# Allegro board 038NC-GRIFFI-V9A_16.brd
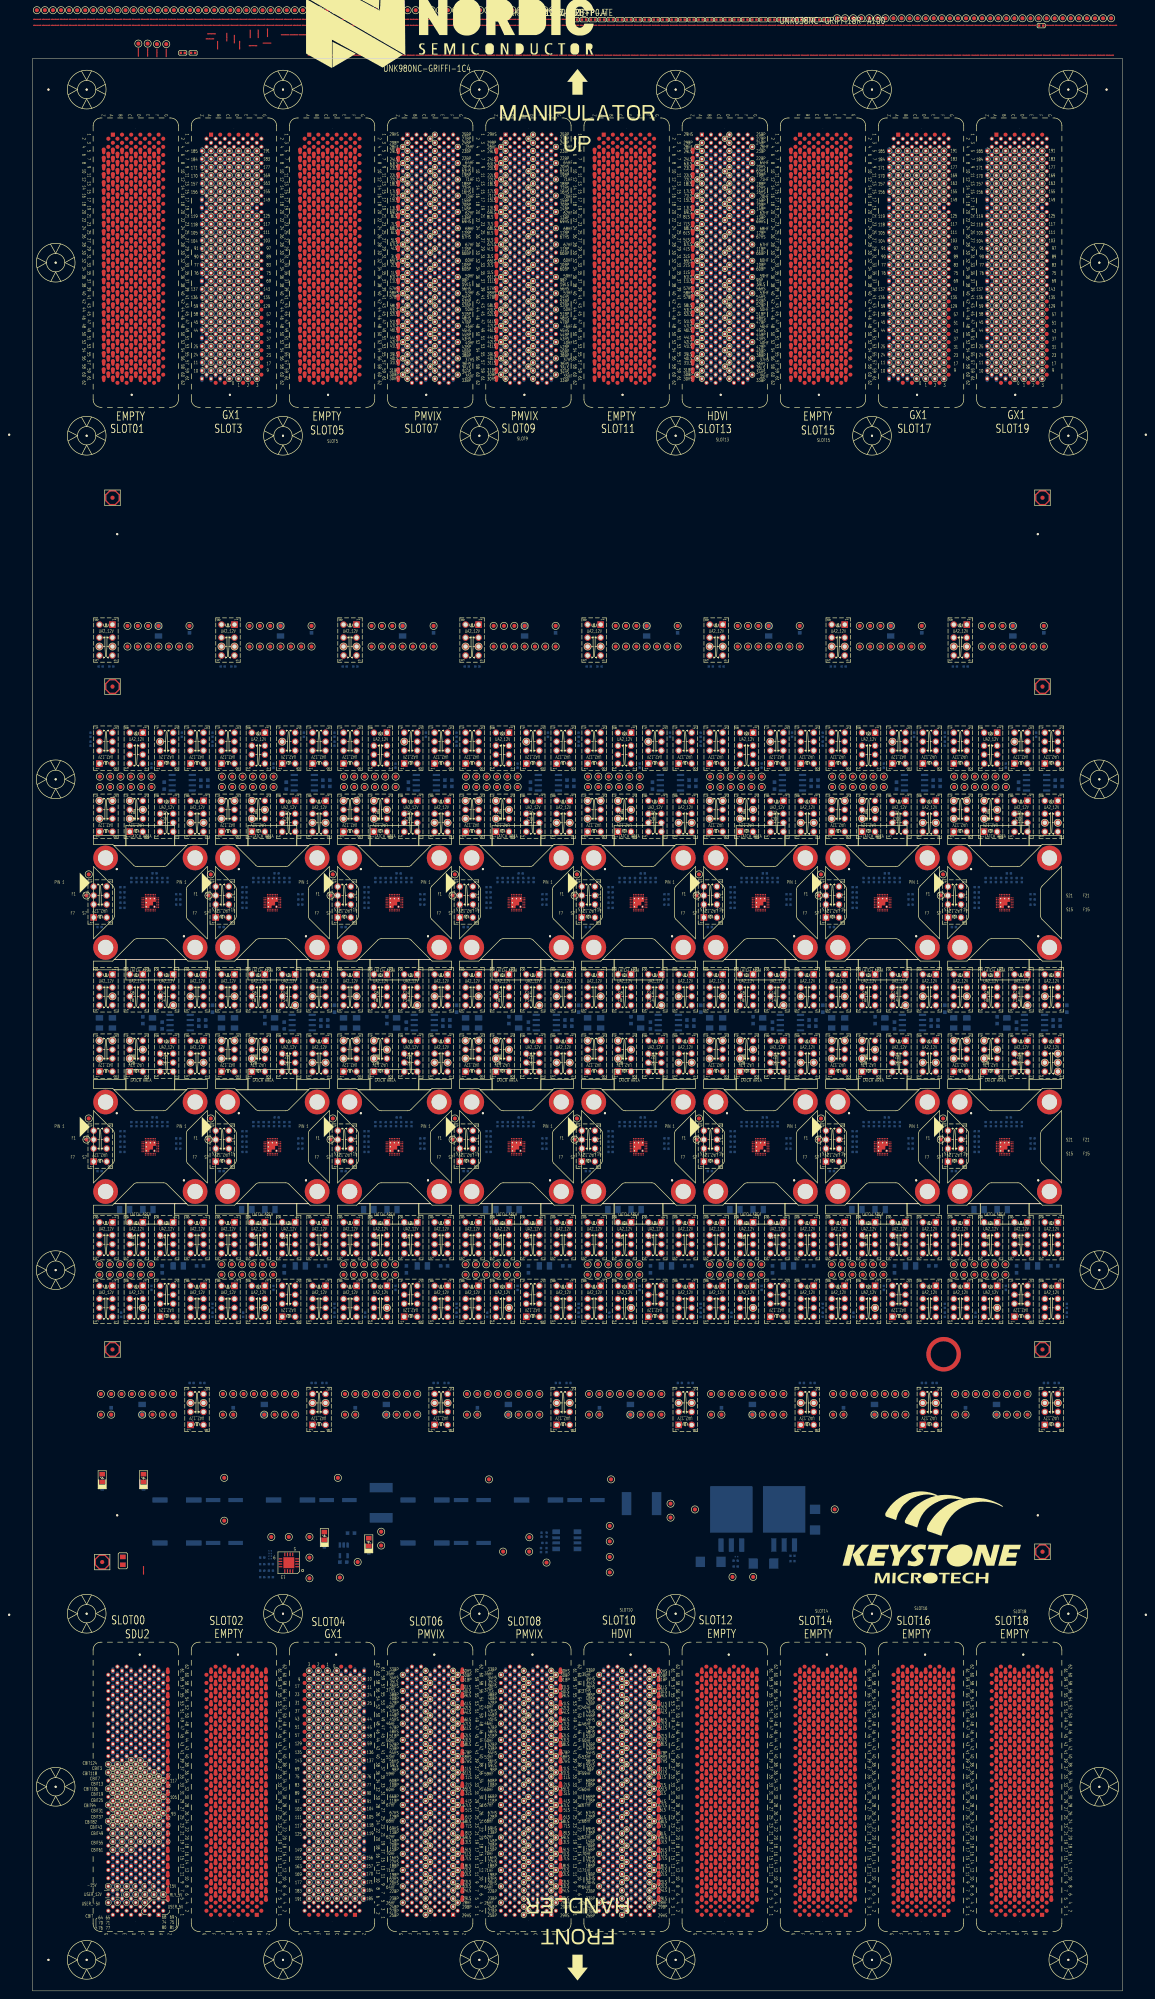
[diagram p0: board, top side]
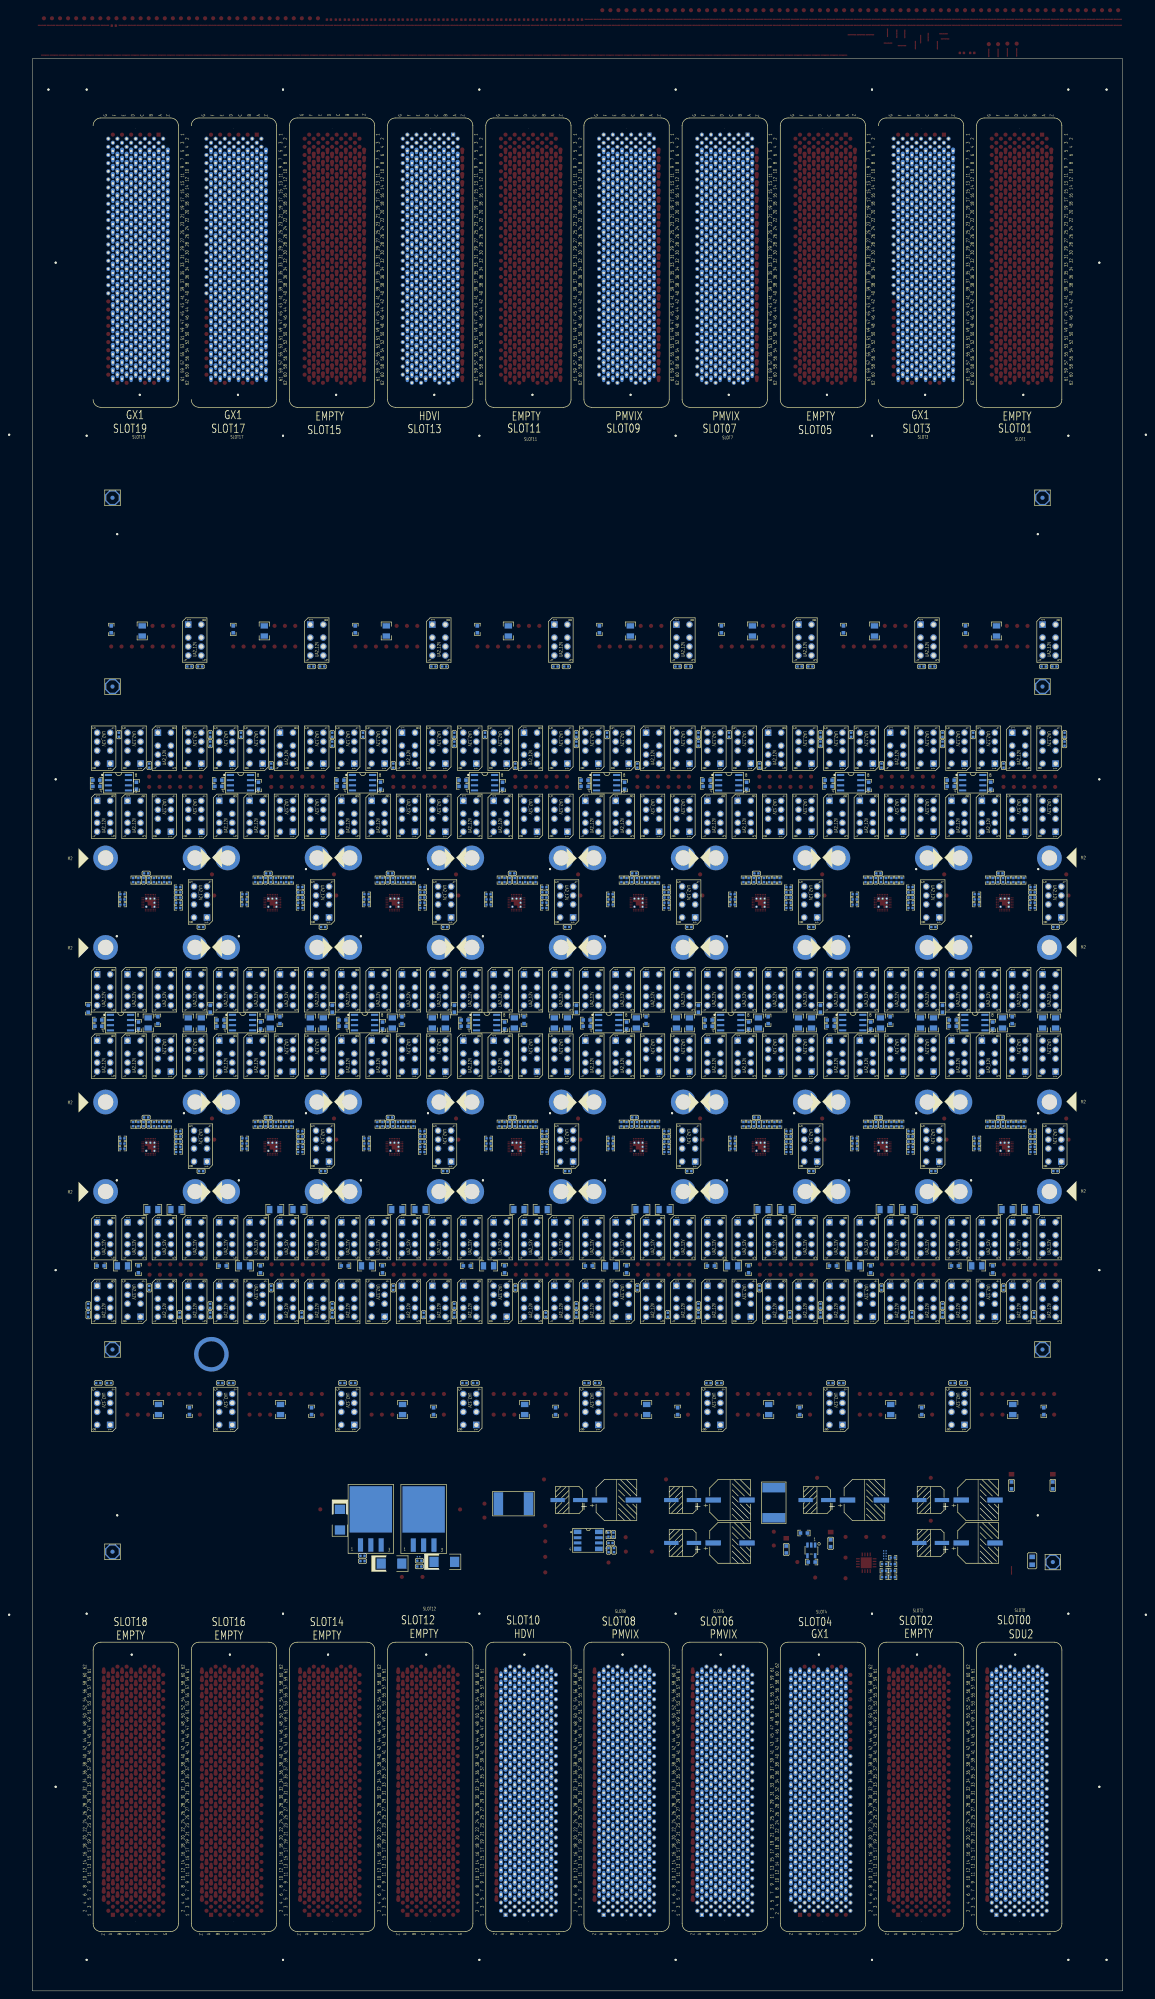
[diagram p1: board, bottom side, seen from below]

Outline 267.97 x 474.98 mm; copper layers: TOP, L02_GND, L03_SIGNAL, L04_GND, L05_SIGNAL, L06_GND, L07_SIGNAL, L08_GND, L09_PWR, L10_PWR, L11_GND, L12_PWR, L13_PWR, L14_GND, L15_USER, L16_CBIT, L17_GND, L18_PWR, L19_PWR, L20_GND, L21_PWR, L22_PWR, L23_GND, L24_SIGNAL, L25_GND, L26_SIGNAL, L27_GND, L28_SIGNAL, L29_GND, L30_SIGNAL, L31_GND, BOTTOM. Coordinates in mm from the lower left corner of the outline.

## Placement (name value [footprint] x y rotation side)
BC1  100U-50-E-S-6.6X6.6  [EC_6P3X7P7MM_S]  75.12 120.65 270 bottom
BC2  47U-100-E-S10X10-NI  [ECS_10X10MM_H10P5]  63.45 120.65 90 bottom
BC3  100U-50-E-S-6.6X6.6  [EC_6P3X7P7MM_S]  108.14 110.11 270 bottom
BC4  47U-100-E-S10X10-NI  [ECS_10X10MM_H10P5]  96.47 110.11 90 bottom
BC5  100U-50-E-S-6.6X6.6  [EC_6P3X7P7MM_S]  47.18 120.65 270 bottom
BC6  47U-100-E-S10X10-NI  [ECS_10X10MM_H10P5]  35.51 120.65 90 bottom
BC7  100U-50-E-S-6.6X6.6  [EC_6P3X7P7MM_S]  108.14 120.65 270 bottom
BC8  47U-100-E-S10X10-NI  [ECS_10X10MM_H10P5]  96.47 120.65 90 bottom
BC10  47U-100-E-S10X10-NI  [ECS_10X10MM_H10P5]  124.41 120.65 90 bottom
BC11  100U-50-E-S-6.6X6.6  [EC_6P3X7P7MM_S]  136.08 120.65 270 bottom
BC12  47U-100-E-S10X10-NI  [ECS_10X10MM_H10P5]  35.51 110.11 90 bottom
BC13  100U-50-E-S-6.6X6.6  [EC_6P3X7P7MM_S]  47.18 110.11 270 bottom
BD1  BD120-3.5A-S8-LA  [FB0805]  22.23 105.71 90 top
BD2  BD120-3.5A-S8-LA  [FB0805]  22.23 105.71 90 bottom
BR1  560-1-S6  [R0603]  71.76 110.03 270 bottom
BR2  560-1-S6  [R0603]  82.68 108.5 270 bottom
BR3  560-1-S6  [R0603]  27.31 124.25 270 bottom
BR4  1K-1-S6  [R0603]  17.15 124.25 270 bottom
C14  1U-16-X5R-S4-YA  [C0402]  126.4 112.15 90 bottom
C84  1U-16-X6S-S4-TY  [C0402]  56.49 106.51 180 bottom
C85  1U-16-X6S-S4-TY  [C0402]  56.49 103.28 180 bottom
C86  1U-16-X6S-S4-TY  [C0402]  56.49 104.88 180 bottom
C87  0.1U-10-X7R-S4-MU-1  [C0402]  58.62 104.91 0 bottom
C88  0.1U-10-X7R-S4-MU-1  [C0402]  58.62 103.28 0 bottom
C89  0.1U-10-X7R-S4-MU-1  [C0402]  56.49 101.68 180 bottom
C90  100P-50-X8R-S4-KEMET  [C0402]  58.62 101.68 0 bottom
C99  10U-35-T-SC  [CODE_C]  166.73 105.45 180 bottom
C100  10U-35-T-SC  [CODE_C]  179.71 105.04 180 bottom
C101  10U-35-T-SC  [CODE_C]  192.38 115.82 270 bottom
C102  1U-25-X7R-S6-WA  [C0603]  78.31 112.54 0 bottom
C103  1U-25-X7R-S6-WA  [C0603]  76.41 105.41 0 bottom
FD1  FD_040  [FD_040_V2]  17.15 105.41 0 top
FD2  FD_040  [FD_040_V2]  19.69 157.66 0 top
FD3  FD_040  [FD_040_V2]  19.69 320.62 0 top
FD4  FD_040  [FD_040_V2]  19.69 367.03 0 top
FD5  FD_040  [FD_040_V2]  248.29 367.03 0 top
FD6  FD_040  [FD_040_V2]  248.29 320.62 0 top
FD7  FD_040  [FD_040_V2]  248.29 157.66 0 top
FD8  FD_040  [FD_040_V2]  248.29 107.95 0 top
FD9  FD_040  [FD_040_V2]  17.15 105.41 180 bottom
FD10  FD_040  [FD_040_V2]  19.69 157.66 180 bottom
FD11  FD_040  [FD_040_V2]  19.69 320.62 180 bottom
FD12  FD_040  [FD_040_V2]  19.69 367.03 180 bottom
FD13  FD_040  [FD_040_V2]  248.29 367.03 180 bottom
FD14  FD_040  [FD_040_V2]  248.29 320.62 180 bottom
FD15  FD_040  [FD_040_V2]  248.29 157.66 180 bottom
FD16  FD_040  [FD_040_V2]  248.29 107.95 180 bottom
FUSE1  2920L200-2A-S7.98X5.44  [FUSE_2920_H45]  149.73 119.76 0 bottom
FUSE2  2920L200-2A-S7.98X5.44  [FUSE_2920_H45]  85.73 119.99 270 bottom
H1  M3-HOLE  [M3_NPTH169]  20.84 116.9 0 top
H2  M3-HOLE  [M3_NPTH169]  20.84 358.08 0 top
H3  M3-HOLE  [M3_NPTH169]  247.13 358.08 0 top
H4  M3-HOLE  [M3_NPTH169]  247.13 116.9 0 top
LOGO1  -  [LOGO_NC_NORDIC]  98.78 473.44 0 top
LOGO2  -  [LOGO_KT_KSMT]  217.98 104.48 0 top
M1  -  [PG_LTXDX_F_X1_OUTLINE_FULL_V2]  133.99 237.49 0 top
NOREF  -  []  83.93 229.18 90 top
NOREF#2  -  []  87.13 244.47 90 top
NOREF#3  -  []  75.06 203.86 0 top
NOREF#4  -  []  237.13 165.7 90 top
NOREF#5  -  []  92.17 456.29 0 top
NOREF#6  -  []  196.47 304.88 90 top
NOREF#7  -  []  164.98 283.99 0 top
NOREF#8  -  []  64.59 289.34 90 top
NOREF#9  -  []  121.39 301.68 0 top
NOREF#10  -  []  87.13 303.88 90 top
NOREF#11  -  []  124.59 244.47 90 top
NOREF#12  -  []  134.98 223.99 0 top
NOREF#13  -  []  250.89 283.29 90 top
NOREF#14  -  []  158.86 292.54 0 top
NOREF#15  -  []  213.61 203.06 0 top
NOREF#16  -  []  150.18 205.47 90 top
NOREF#17  -  []  106.47 288.14 90 top
NOREF#18  -  []  29.32 208.11 315 top
NOREF#19  -  []  57.13 246.67 90 top
NOREF#20  -  []  210.18 265.47 90 top
NOREF#21  -  []  128.86 307.08 90 top
NOREF#22  -  []  27.13 242.27 90 top
NOREF#23  -  []  117.13 170.1 90 top
NOREF#24  -  []  195.06 269.26 90 top
NOREF#25  -  []  71.4 298.06 90 top
NOREF#26  -  []  94.59 242.27 90 top
NOREF#27  -  []  162.06 167.9 90 top
NOREF#28  -  []  212.82 456.29 0 top
NOREF#29  -  []  218.86 292.54 0 top
NOREF#30  -  []  117.13 301.68 90 top
NOREF#31  -  []  232.1 458.49 0 top
NOREF#32  -  []  87.13 185.73 90 top
NOREF#33  -  []  116.3 396.29 0 top
NOREF#34  -  []  115.97 179.68 90 top
NOREF#35  -  []  139.67 242.27 90 top
NOREF#36  -  []  132.78 117.35 0 top
NOREF#37  -  []  232.08 83.81 0 top
NOREF#38  -  []  45.92 284.14 90 top
NOREF#39  -  []  70.9 237.58 90 top
NOREF#40  -  []  83.93 249.87 0 top
NOREF#41  -  []  38.39 193.49 45 top
NOREF#42  -  []  119.39 209.51 0 top
NOREF#43  -  []  184.59 181.33 90 top
NOREF#44  -  []  229.67 183.53 90 top
NOREF#45  -  []  38.86 173.3 0 top
NOREF#46  -  []  131.4 296.54 90 top
NOREF#47  -  []  232.98 286.49 0 top
NOREF#48  -  []  151.39 171.1 90 top
NOREF#49  -  []  128.31 138.32 90 top
NOREF#50  -  []  16.47 231.38 90 top
NOREF#51  -  []  185.02 225.18 0 top
NOREF#52  -  []  72.67 392.33 90 top
NOREF#53  -  []  136.47 225.98 0 top
NOREF#54  -  []  149.42 18.69 0 top
NOREF#55  -  []  121.39 188.93 0 top
NOREF#56  -  []  93.43 164.05 90 top
NOREF#57  -  []  121.39 168.9 90 top
NOREF#58  -  []  19.67 328.26 90 top
NOREF#59  -  []  57.13 185.73 90 top
NOREF#60  -  []  45.06 267.06 90 top
NOREF#61  -  []  196.47 225.98 0 top
NOREF#62  -  []  87.13 301.68 90 top
NOREF#63  -  []  207.36 208.69 0 top
NOREF#64  -  []  252.06 289.34 90 top
NOREF#65  -  []  200.48 270.77 0 top
NOREF#66  -  []  87.13 165.7 90 top
NOREF#67  -  []  151.67 18.69 90 top
NOREF#68  -  []  72.06 242.27 90 top
NOREF#69  -  []  147.13 181.33 90 top
NOREF#70  -  []  45.92 225.18 90 top
NOREF#71  -  []  44.99 281.49 90 top
NOREF#72  -  []  20.22 174.1 0 top
NOREF#73  -  []  135.06 203.86 90 top
NOREF#74  -  []  188.66 177.76 90 top
NOREF#75  -  []  79.67 170.1 90 top
NOREF#76  -  []  42.06 170.1 90 top
NOREF#77  -  []  130.89 179.68 90 top
NOREF#78  -  []  147.36 208.69 0 top
NOREF#79  -  []  127.36 333.84 90 top
NOREF#80  -  []  180.84 300.88 90 top
NOREF#81  -  []  244.59 287.14 90 top
NOREF#82  -  []  140.74 275.74 0 top
NOREF#83  -  []  68.86 304.88 90 top
NOREF#84  -  []  158.66 177.76 90 top
NOREF#85  -  []  61.4 188.93 0 top
NOREF#86  -  []  188.86 304.88 90 top
NOREF#87  -  []  164.55 18.69 0 top
NOREF#88  -  []  184.59 185.73 90 top
NOREF#89  -  []  61.4 249.87 0 top
NOREF#90  -  []  181.39 307.08 90 top
NOREF#91  -  []  229.67 167.9 90 top
NOREF#92  -  []  169.67 328.26 90 top
NOREF#93  -  []  83.93 284.94 0 top
NOREF#94  -  []  248.86 307.08 90 top
NOREF#95  -  []  58.35 207.84 315 top
NOREF#96  -  []  147.13 301.68 90 top
NOREF#97  -  []  131.02 336.66 0 top
NOREF#98  -  []  27.64 268.84 0 top
NOREF#99  -  []  237.13 301.68 90 top
NOREF#100  -  []  19.67 332.66 90 top
NOREF#101  -  []  208.35 267.84 315 top
NOREF#102  -  []  173.93 309.28 0 top
NOREF#103  -  []  211.01 266.29 90 top
NOREF#104  -  []  205.94 234.38 0 top
NOREF#105  -  []  57.82 106.54 0 top
NOREF#106  -  []  192.06 289.34 90 top
NOREF#107  -  []  248.86 301.68 0 top
NOREF#108  -  []  48.48 310.08 0 top
NOREF#109  -  []  205.97 240.62 90 top
NOREF#110  -  []  19.67 185.73 90 top
NOREF#111  -  []  162.66 103.55 90 top
NOREF#112  -  []  43.91 396.29 0 top
NOREF#113  -  []  119.29 267.51 45 top
NOREF#114  -  []  102.06 185.73 90 top
NOREF#115  -  []  241.39 301.68 90 top
NOREF#116  -  []  98.31 138.32 90 top
NOREF#117  -  []  136.47 288.14 90 top
NOREF#118  -  []  123.43 164.05 90 top
NOREF#119  -  []  192.06 242.27 90 top
NOREF#120  -  []  15.06 263.86 90 top
NOREF#121  -  []  22.99 188.49 90 top
NOREF#122  -  []  225.06 263.86 0 top
NOREF#123  -  []  101.02 174.1 0 top
NOREF#124  -  []  40.9 237.58 90 top
NOREF#125  -  []  117.79 209.51 0 top
NOREF#126  -  []  151.39 165.7 90 top
NOREF#127  -  []  210.84 164.9 90 top
NOREF#128  -  []  192.06 165.7 90 top
NOREF#129  -  []  72.06 244.47 90 top
NOREF#130  -  []  210.65 236.45 90 top
NOREF#131  -  []  16.47 229.18 90 top
NOREF#132  -  []  208.37 267.15 315 top
NOREF#133  -  []  91.4 171.1 90 top
NOREF#134  -  []  248.86 139.12 90 top
NOREF#135  -  []  240.18 205.47 90 top
NOREF#136  -  []  181.39 301.68 0 top
NOREF#137  -  []  95.02 225.18 0 top
NOREF#138  -  []  194.51 203.06 90 top
NOREF#139  -  []  15.07 283.29 90 top
NOREF#140  -  []  153.43 179.68 90 top
NOREF#141  -  []  90.84 164.9 90 top
NOREF#142  -  []  120.26 120.65 0 top
NOREF#143  -  []  108.48 250.67 0 top
NOREF#144  -  []  14.99 283.99 0 top
NOREF#145  -  []  228.36 240.62 90 top
NOREF#146  -  []  17.99 196.49 90 top
NOREF#147  -  []  232.98 188.49 90 top
NOREF#148  -  []  172.98 248.49 90 top
NOREF#149  -  []  42.48 284.14 0 top
NOREF#150  -  []  113.93 309.28 0 top
NOREF#151  -  []  90.84 300.88 90 top
NOREF#152  -  []  123.41 234.38 0 top
NOREF#153  -  []  117.13 165.7 90 top
NOREF#154  -  []  71.4 296.54 90 top
NOREF#155  -  []  120.67 176.51 90 top
NOREF#156  -  []  244.59 181.33 90 top
NOREF#157  -  []  27.13 185.73 90 top
NOREF#158  -  []  61.2 115.65 0 top
NOREF#159  -  []  57.64 268.84 0 top
NOREF#160  -  []  110.74 275.74 0 top
NOREF#161  -  []  211.39 188.93 0 top
NOREF#162  -  []  225.06 209.26 90 top
NOREF#163  -  []  109.94 300.88 0 top
NOREF#164  -  []  61.4 292.54 0 top
NOREF#165  -  []  210.18 265.86 90 top
NOREF#166  -  []  151.01 206.29 90 top
NOREF#167  -  []  207.13 185.73 90 top
NOREF#168  -  []  191.4 298.06 90 top
NOREF#169  -  []  93.41 189.73 0 top
NOREF#170  -  []  76.47 284.94 90 top
NOREF#171  -  []  252.06 284.94 90 top
NOREF#172  -  []  241.39 165.7 0 top
NOREF#173  -  []  83.93 225.98 90 top
NOREF#174  -  []  203.93 231.38 90 top
NOREF#175  -  []  233.93 188.93 0 top
NOREF#176  -  []  143.93 225.98 90 top
NOREF#177  -  []  153.43 240.62 90 top
NOREF#178  -  []  78.48 250.67 0 top
NOREF#179  -  []  25.97 179.68 90 top
NOREF#180  -  []  217.23 199.24 90 top
NOREF#181  -  []  113.38 225.18 90 top
NOREF#182  -  []  89.29 267.51 45 top
NOREF#183  -  []  188.39 193.49 45 top
NOREF#184  -  []  132.06 246.67 90 top
NOREF#185  -  []  149.29 267.51 45 top
NOREF#186  -  []  139.67 181.33 90 top
NOREF#187  -  []  27.13 306.08 90 top
NOREF#188  -  []  144.63 116.76 0 top
NOREF#189  -  []  250.89 237.58 90 top
NOREF#190  -  []  70.89 224.33 90 top
NOREF#191  -  []  196.47 188.93 0 top
NOREF#192  -  []  150.84 300.88 90 top
NOREF#193  -  []  135.58 458.49 0 top
NOREF#194  -  []  76.47 335.86 0 top
NOREF#195  -  []  177.13 170.1 90 top
NOREF#196  -  []  79.94 300.88 0 top
NOREF#197  -  []  136.47 173.3 0 top
NOREF#198  -  []  235.88 237.76 90 top
NOREF#199  -  []  134.51 203.06 90 top
NOREF#200  -  []  59.32 208.11 315 top
NOREF#201  -  []  59.29 267.51 45 top
NOREF#202  -  []  192.38 113.28 90 top
NOREF#203  -  []  57.82 107.84 0 top
NOREF#204  -  []  225.06 203.86 90 top
NOREF#205  -  []  22.53 251.52 0 top
NOREF#206  -  []  109.94 164.9 0 top
NOREF#207  -  []  168.48 250.67 0 top
NOREF#208  -  []  33.97 14.59 90 top
NOREF#209  -  []  78.36 164.05 90 top
NOREF#210  -  []  233.93 284.94 0 top
NOREF#211  -  []  184.59 242.27 90 top
NOREF#212  -  []  169.67 167.9 90 top
NOREF#213  -  []  76.47 231.38 90 top
NOREF#214  -  []  38.86 188.93 0 top
NOREF#215  -  []  23.93 249.87 0 top
NOREF#216  -  []  88.65 266.87 45 top
NOREF#217  -  []  160.89 224.33 90 top
NOREF#218  -  []  104.99 221.49 90 top
NOREF#219  -  []  85.94 234.38 0 top
NOREF#220  -  []  77.99 256.49 90 top
NOREF#221  -  []  222.06 185.73 90 top
NOREF#222  -  []  147.13 244.47 90 top
NOREF#223  -  []  42.06 181.33 90 top
NOREF#224  -  []  195.06 263.86 90 top
NOREF#225  -  []  120.18 265.86 90 top
NOREF#226  -  []  28.35 207.84 45 top
NOREF#227  -  []  94.59 185.73 90 top
NOREF#228  -  []  203.93 290.34 90 top
NOREF#229  -  []  240.33 266.14 90 top
NOREF#230  -  []  31.4 171.1 90 top
NOREF#231  -  []  105.06 267.06 90 top
NOREF#232  -  []  20.61 142.44 90 top
NOREF#233  -  []  235.94 189.73 0 top
NOREF#234  -  []  159.71 458.49 0 top
NOREF#235  -  []  16.47 288.14 90 top
NOREF#236  -  []  139.67 185.73 90 top
NOREF#237  -  []  81.95 111.4 0 top
NOREF#238  -  []  4.17 164.05 90 top
NOREF#239  -  []  244.59 185.73 90 top
NOREF#240  -  []  175.97 179.68 90 top
NOREF#241  -  []  237.13 167.9 90 top
NOREF#242  -  []  200.73 215.74 0 top
NOREF#243  -  []  41.4 295.64 90 top
NOREF#244  -  []  34.6 230.38 90 top
NOREF#245  -  []  158.86 144.52 90 top
NOREF#246  -  []  252.06 183.53 90 top
NOREF#247  -  []  118.37 207.15 315 top
NOREF#248  -  []  106.38 389.27 90 top
NOREF#249  -  []  158.39 193.49 45 top
NOREF#250  -  []  116.29 20.69 90 top
NOREF#251  -  []  26.58 127.15 0 top
NOREF#252  -  []  45.06 207.06 90 top
NOREF#253  -  []  208.35 267.84 45 top
NOREF#254  -  []  102.06 228.18 90 top
NOREF#255  -  []  23.93 188.93 0 top
NOREF#256  -  []  227.98 256.49 90 top
NOREF#257  -  []  140.48 210.77 0 top
NOREF#258  -  []  35.02 284.14 0 top
NOREF#259  -  []  38.86 292.54 0 top
NOREF#260  -  []  154.59 228.18 90 top
NOREF#261  -  []  181.39 165.7 0 top
NOREF#262  -  []  222.06 230.38 90 top
NOREF#263  -  []  57.13 165.7 90 top
NOREF#264  -  []  209.38 209.51 0 top
NOREF#265  -  []  71.03 110.73 90 top
NOREF#266  -  []  17.99 278.49 0 top
NOREF#267  -  []  49.95 300.88 0 top
NOREF#268  -  []  158.86 301.68 0 top
NOREF#269  -  []  178.35 267.84 45 top
NOREF#270  -  []  228.36 224.33 90 top
NOREF#271  -  []  196.47 284.94 0 top
NOREF#272  -  []  140.43 456.29 90 top
NOREF#273  -  []  248.66 177.76 90 top
NOREF#274  -  []  98.86 188.93 0 top
NOREF#275  -  []  16.42 124.95 90 top
NOREF#276  -  []  165.92 300.88 90 top
NOREF#277  -  []  239.32 268.11 315 top
NOREF#278  -  []  188.86 292.54 0 top
NOREF#279  -  []  113.93 225.98 90 top
NOREF#280  -  []  31.01 266.29 90 top
NOREF#281  -  []  13.66 262.21 90 top
NOREF#282  -  []  240.18 265.86 90 top
NOREF#283  -  []  21.07 240.62 90 top
NOREF#284  -  []  66.45 115.65 0 top
NOREF#285  -  []  125.02 225.18 0 top
NOREF#286  -  []  148.37 267.15 315 top
NOREF#287  -  []  25.7 258.99 90 top
NOREF#288  -  []  235.97 179.68 90 top
NOREF#289  -  []  155.02 300.88 0 top
NOREF#290  -  []  49.67 185.73 90 top
NOREF#291  -  []  59.29 207.51 45 top
NOREF#292  -  []  138.48 250.67 0 top
NOREF#293  -  []  188.31 300.88 90 top
NOREF#294  -  []  110.48 270.77 0 top
NOREF#295  -  []  128.31 300.88 90 top
NOREF#296  -  []  120.34 206.14 90 top
NOREF#297  -  []  109.67 181.33 90 top
NOREF#298  -  []  194.98 190.99 90 top
NOREF#299  -  []  76.47 229.18 90 top
NOREF#300  -  []  135.15 107.82 90 top
NOREF#301  -  []  42.61 189.73 0 top
NOREF#302  -  []  147.13 246.67 90 top
NOREF#303  -  []  151.39 301.68 0 top
NOREF#304  -  []  85.94 293.34 0 top
NOREF#305  -  []  195.06 267.06 90 top
NOREF#306  -  []  83.38 284.14 90 top
NOREF#307  -  []  87.79 209.51 0 top
NOREF#308  -  []  207.78 209.51 0 top
NOREF#309  -  []  136.47 290.34 90 top
NOREF#310  -  []  28.65 266.87 45 top
NOREF#311  -  []  85.73 116.29 90 top
NOREF#312  -  []  229.67 328.26 90 top
NOREF#313  -  []  101.02 250.67 0 top
NOREF#314  -  []  247.36 333.84 90 top
NOREF#315  -  []  147.63 268.84 0 top
NOREF#316  -  []  252.06 225.98 90 top
NOREF#317  -  []  215.02 300.88 0 top
NOREF#318  -  []  44.4 110.11 0 top
NOREF#319  -  []  113.93 284.94 0 top
NOREF#320  -  []  90.18 265.86 90 top
NOREF#321  -  []  190.89 283.29 90 top
NOREF#322  -  []  143.93 231.38 90 top
NOREF#323  -  []  118.65 266.87 45 top
NOREF#324  -  []  121.39 307.08 90 top
NOREF#325  -  []  154.59 183.53 90 top
NOREF#326  -  []  38.86 301.68 90 top
NOREF#327  -  []  153.41 174.1 0 top
NOREF#328  -  []  15.07 251.52 0 top
NOREF#329  -  []  16.15 123.41 90 top
NOREF#330  -  []  241.39 168.9 90 top
NOREF#331  -  []  165.06 263.86 90 top
NOREF#332  -  []  143.38 225.18 90 top
NOREF#333  -  []  53.93 225.98 0 top
NOREF#334  -  []  218.86 249.87 0 top
NOREF#335  -  []  23.93 288.14 90 top
NOREF#336  -  []  17.99 256.49 90 top
NOREF#337  -  []  97.55 263.78 0 top
NOREF#338  -  []  72.48 284.14 0 top
NOREF#339  -  []  118.37 267.15 315 top
NOREF#340  -  []  72.06 165.7 90 top
NOREF#341  -  []  164.56 396.29 0 top
NOREF#342  -  []  120.93 392.33 90 top
NOREF#343  -  []  175.94 189.73 0 top
NOREF#344  -  []  210.18 205.86 90 top
NOREF#345  -  []  0 474.98 0 top
NOREF#346  -  []  58.12 107.52 0 top
NOREF#347  -  []  169.67 165.7 90 top
NOREF#348  -  []  181.39 168.9 90 top
NOREF#349  -  []  169.67 170.1 90 top
NOREF#350  -  []  108.36 283.29 90 top
NOREF#351  -  []  190.89 239.1 90 top
NOREF#352  -  []  63.19 457.2 0 top
NOREF#353  -  []  178.65 206.87 45 top
NOREF#354  -  []  248.86 233.58 0 top
NOREF#355  -  []  128.86 292.54 0 top
NOREF#356  -  []  58.12 108.17 0 top
NOREF#357  -  []  195.06 203.86 0 top
NOREF#358  -  []  46.47 335.86 0 top
NOREF#359  -  []  79.28 18.69 0 top
NOREF#360  -  []  177.13 167.9 90 top
NOREF#361  -  []  192.06 183.53 90 top
NOREF#362  -  []  233.93 225.98 0 top
NOREF#363  -  []  82.99 248.49 90 top
NOREF#364  -  []  75.56 104.96 90 top
NOREF#365  -  []  162.06 170.1 90 top
NOREF#366  -  []  207.13 303.88 90 top
NOREF#367  -  []  25.39 17.15 0 top
NOREF#368  -  []  61.4 301.68 90 top
NOREF#369  -  []  63.41 250.67 0 top
NOREF#370  -  []  252.06 170.1 90 top
NOREF#371  -  []  139.67 330.46 90 top
NOREF#372  -  []  237.13 246.67 90 top
NOREF#373  -  []  181.39 171.1 90 top
NOREF#374  -  []  58.35 267.84 45 top
NOREF#375  -  []  27.13 303.88 90 top
NOREF#376  -  []  19.67 244.47 90 top
NOREF#377  -  []  177.13 165.7 90 top
NOREF#378  -  []  60.34 206.14 90 top
NOREF#379  -  []  143.93 284.94 90 top
NOREF#380  -  []  220.89 240.62 90 top
NOREF#381  -  []  197.69 456.29 0 top
NOREF#382  -  []  225.06 267.06 90 top
NOREF#383  -  []  16.47 284.94 90 top
NOREF#384  -  []  64.59 246.67 90 top
NOREF#385  -  []  31.36 120.65 0 top
NOREF#386  -  []  27.13 246.67 90 top
NOREF#387  -  []  241.39 301.68 0 top
NOREF#388  -  []  206.96 208.69 0 top
NOREF#389  -  []  22.53 283.29 90 top
NOREF#390  -  []  25.95 189.73 0 top
NOREF#391  -  []  218.86 173.3 0 top
NOREF#392  -  []  139.67 167.9 90 top
NOREF#393  -  []  128.86 144.52 90 top
NOREF#394  -  []  214.59 244.47 90 top
NOREF#395  -  []  138.36 283.29 90 top
NOREF#396  -  []  175.7 258.99 90 top
NOREF#397  -  []  123.43 300.03 90 top
NOREF#398  -  []  247.55 263.78 0 top
NOREF#399  -  []  46.47 301.68 90 top
NOREF#400  -  []  108.36 164.05 90 top
NOREF#401  -  []  195.06 263.86 0 top
NOREF#402  -  []  199.67 185.73 90 top
NOREF#403  -  []  199.67 330.46 90 top
NOREF#404  -  []  172.46 106.41 0 top
NOREF#405  -  []  183.41 293.34 0 top
NOREF#406  -  []  88.35 267.84 315 top
NOREF#407  -  []  183.84 458.49 0 top
NOREF#408  -  []  14.91 16.49 0 top
NOREF#409  -  []  229.94 300.88 0 top
NOREF#410  -  []  107.99 278.49 0 top
NOREF#411  -  []  175.94 293.34 0 top
NOREF#412  -  []  52.99 286.49 0 top
NOREF#413  -  []  101.17 456.29 0 top
NOREF#414  -  []  224.98 281.49 90 top
NOREF#415  -  []  11.63 164.05 90 top
NOREF#416  -  []  16.47 304.88 90 top
NOREF#417  -  []  224.98 221.49 90 top
NOREF#418  -  []  88.65 206.87 45 top
NOREF#419  -  []  119.39 269.51 0 top
NOREF#420  -  []  138.48 174.1 0 top
NOREF#421  -  []  147.13 165.7 90 top
NOREF#422  -  []  11.02 189.73 0 top
NOREF#423  -  []  117.13 242.27 90 top
NOREF#424  -  []  91.01 266.29 90 top
NOREF#425  -  []  15.06 263.86 0 top
NOREF#426  -  []  214.59 225.98 90 top
NOREF#427  -  []  117.64 208.84 0 top
NOREF#428  -  []  46.47 284.94 0 top
NOREF#429  -  []  184.59 228.18 90 top
NOREF#430  -  []  237.78 209.51 0 top
NOREF#431  -  []  166.47 225.98 90 top
NOREF#432  -  []  40.9 239.1 90 top
NOREF#433  -  []  94.59 225.98 90 top
NOREF#434  -  []  213.61 263.06 0 top
NOREF#435  -  []  40.9 224.33 90 top
NOREF#436  -  []  202.98 188.49 90 top
NOREF#437  -  []  248.86 304.88 90 top
NOREF#438  -  []  90.67 176.51 90 top
NOREF#439  -  []  68.04 456.29 0 top
NOREF#440  -  []  136.47 301.68 90 top
NOREF#441  -  []  173.93 288.14 90 top
NOREF#442  -  []  31.4 233.58 0 top
NOREF#443  -  []  191.02 336.66 0 top
NOREF#444  -  []  124.59 242.27 90 top
NOREF#445  -  []  213.41 174.1 0 top
NOREF#446  -  []  203.38 284.14 90 top
NOREF#447  -  []  118.35 267.84 315 top
NOREF#448  -  []  184.59 183.53 90 top
NOREF#449  -  []  91.4 188.93 0 top
NOREF#450  -  []  98.31 300.88 90 top
NOREF#451  -  []  220.89 239.1 90 top
NOREF#452  -  []  137.98 256.49 90 top
NOREF#453  -  []  207.13 244.47 90 top
NOREF#454  -  []  163.01 240.57 90 top
NOREF#455  -  []  167.98 196.49 90 top
NOREF#456  -  []  143.38 284.14 90 top
NOREF#457  -  []  55.97 326.61 90 top
NOREF#458  -  []  173.93 290.34 90 top
NOREF#459  -  []  222.06 167.9 90 top
NOREF#460  -  []  210.84 300.88 90 top
NOREF#461  -  []  92.32 120.65 0 top
NOREF#462  -  []  241.39 188.93 0 top
NOREF#463  -  []  61.01 266.29 90 top
NOREF#464  -  []  220.89 283.29 90 top
NOREF#465  -  []  137.21 143.34 90 top
NOREF#466  -  []  98.86 139.12 90 top
NOREF#467  -  []  222.06 225.98 90 top
NOREF#468  -  []  38.86 249.87 0 top
NOREF#469  -  []  235.97 326.61 90 top
NOREF#470  -  []  75.92 284.14 90 top
NOREF#471  -  []  207.41 300.88 0 top
NOREF#472  -  []  102.48 284.14 0 top
NOREF#473  -  []  164.98 221.49 90 top
NOREF#474  -  []  106.36 14.59 90 top
NOREF#475  -  []  106.47 188.93 0 top
NOREF#476  -  []  23.93 290.34 90 top
NOREF#477  -  []  244.59 289.34 90 top
NOREF#478  -  []  235.97 240.62 90 top
NOREF#479  -  []  199.67 332.66 90 top
NOREF#480  -  []  165.06 207.06 90 top
NOREF#481  -  []  197.98 196.49 90 top
NOREF#482  -  []  15.06 209.26 90 top
NOREF#483  -  []  227.98 218.49 0 top
NOREF#484  -  []  211.39 165.7 90 top
NOREF#485  -  []  166.47 231.38 90 top
NOREF#486  -  []  64.59 242.27 90 top
NOREF#487  -  []  118.35 207.84 45 top
NOREF#488  -  []  55.95 189.73 0 top
NOREF#489  -  []  208.65 266.87 45 top
NOREF#490  -  []  98.86 304.88 90 top
NOREF#491  -  []  165.06 269.26 90 top
NOREF#492  -  []  173.56 456.29 0 top
NOREF#493  -  []  31.4 301.68 0 top
NOREF#494  -  []  38.86 301.68 0 top
NOREF#495  -  []  93.41 174.1 0 top
NOREF#496  -  []  228.48 250.67 0 top
NOREF#497  -  []  104.84 117.35 90 top
NOREF#498  -  []  135.92 225.18 90 top
NOREF#499  -  []  71.02 189.73 0 top
NOREF#500  -  []  93.41 293.34 0 top
NOREF#501  -  []  173.93 173.3 0 top
NOREF#502  -  []  164.98 223.99 0 top
NOREF#503  -  []  158.86 139.12 0 top
NOREF#504  -  []  232.98 248.49 90 top
NOREF#505  -  []  26.56 224.33 90 top
NOREF#506  -  []  68.86 292.54 0 top
NOREF#507  -  []  31.36 110.11 0 top
NOREF#508  -  []  166.47 284.94 90 top
NOREF#509  -  []  207.63 208.84 0 top
NOREF#510  -  []  79.28 18.69 90 top
NOREF#511  -  []  123.61 263.06 0 top
NOREF#512  -  []  188.86 249.87 0 top
NOREF#513  -  []  77.04 456.29 0 top
NOREF#514  -  []  26.96 268.69 0 top
NOREF#515  -  []  188.86 301.68 0 top
NOREF#516  -  []  226.47 288.14 90 top
NOREF#517  -  []  162.06 183.53 90 top
NOREF#518  -  []  229.67 242.27 90 top
NOREF#519  -  []  49.67 246.67 90 top
NOREF#520  -  []  56.96 268.69 0 top
NOREF#521  -  []  200.73 275.74 0 top
NOREF#522  -  []  123.41 250.67 0 top
NOREF#523  -  []  134.98 281.49 90 top
NOREF#524  -  []  147.13 242.27 90 top
NOREF#525  -  []  150.33 206.14 90 top
NOREF#526  -  []  177.13 185.73 90 top
NOREF#527  -  []  170.73 275.74 0 top
NOREF#528  -  []  203.93 288.14 90 top
NOREF#529  -  []  14.99 253.49 90 top
NOREF#530  -  []  177.36 208.69 0 top
NOREF#531  -  []  195.92 284.14 90 top
NOREF#532  -  []  31.4 165.7 0 top
NOREF#533  -  []  132.06 225.98 90 top
NOREF#534  -  []  87.13 306.08 90 top
NOREF#535  -  []  113.93 284.94 90 top
NOREF#536  -  []  203.93 188.93 0 top
NOREF#537  -  []  30.34 206.14 90 top
NOREF#538  -  []  104.99 283.99 0 top
NOREF#539  -  []  165.92 225.18 90 top
NOREF#540  -  []  121.39 165.7 0 top
NOREF#541  -  []  181.01 206.29 90 top
NOREF#542  -  []  243.43 300.03 90 top
NOREF#543  -  []  176.71 103.44 90 top
NOREF#544  -  []  172.98 286.49 0 top
NOREF#545  -  []  209.32 208.11 315 top
NOREF#546  -  []  252.06 287.14 90 top
NOREF#547  -  []  237.63 268.84 0 top
NOREF#548  -  []  60.19 265.86 90 top
NOREF#549  -  []  237.63 208.84 0 top
NOREF#550  -  []  37.24 259.24 90 top
NOREF#551  -  []  250.83 14.59 90 top
NOREF#552  -  []  151.01 266.69 90 top
NOREF#553  -  []  72.06 185.73 90 top
NOREF#554  -  []  190.89 240.62 90 top
NOREF#555  -  []  68.86 301.68 90 top
NOREF#556  -  []  25.39 17.15 90 top
NOREF#557  -  []  175.94 234.38 0 top
NOREF#558  -  []  41.02 250.67 0 top
NOREF#559  -  []  164.98 281.49 90 top
NOREF#560  -  []  134.51 263.06 90 top
NOREF#561  -  []  34.6 284.94 90 top
NOREF#562  -  []  43.91 456.29 90 top
NOREF#563  -  []  150.33 266.14 90 top
NOREF#564  -  []  42.06 167.9 90 top
NOREF#565  -  []  67.55 203.78 0 top
NOREF#566  -  []  124.59 246.67 90 top
NOREF#567  -  []  177.13 306.08 90 top
NOREF#568  -  []  27.13 181.33 90 top
NOREF#569  -  []  71.02 336.66 0 top
NOREF#570  -  []  121.39 304.88 90 top
NOREF#571  -  []  237.13 242.27 90 top
NOREF#572  -  []  131.02 250.67 0 top
NOREF#573  -  []  79.67 244.47 90 top
NOREF#574  -  []  199.94 164.9 0 top
NOREF#575  -  []  153.41 189.73 0 top
NOREF#576  -  []  191.02 250.67 0 top
NOREF#577  -  []  58.12 106.22 0 top
NOREF#578  -  []  177.13 183.53 90 top
NOREF#579  -  []  14.99 221.49 90 top
NOREF#580  -  []  74.99 253.49 90 top
NOREF#581  -  []  176.71 106.64 0 top
NOREF#582  -  []  57.41 300.88 0 top
NOREF#583  -  []  61.4 165.7 0 top
NOREF#584  -  []  151.39 301.68 90 top
NOREF#585  -  []  113.93 225.98 0 top
NOREF#586  -  []  117.36 268.69 0 top
NOREF#587  -  []  15.06 267.06 90 top
NOREF#588  -  []  150.67 176.51 90 top
NOREF#589  -  []  139.67 244.47 90 top
NOREF#590  -  []  163.42 19.69 90 top
NOREF#591  -  []  184.59 246.67 90 top
NOREF#592  -  []  75.06 207.06 90 top
NOREF#593  -  []  121.01 266.69 90 top
NOREF#594  -  []  154.83 116.76 90 top
NOREF#595  -  []  128.86 301.68 90 top
NOREF#596  -  []  38.86 233.58 0 top
NOREF#597  -  []  64.59 244.47 90 top
NOREF#598  -  []  36.61 138.32 90 top
NOREF#599  -  []  19.78 456.29 90 top
NOREF#600  -  []  243.43 179.68 90 top
NOREF#601  -  []  222.06 170.1 90 top
NOREF#602  -  []  16.47 335.86 0 top
NOREF#603  -  []  22.53 310.93 0 top
NOREF#604  -  []  28.53 240.62 90 top
NOREF#605  -  []  235.94 250.67 0 top
NOREF#606  -  []  106.47 304.88 90 top
NOREF#607  -  []  102.06 287.14 90 top
NOREF#608  -  []  50.49 210.77 0 top
NOREF#609  -  []  248.86 249.87 0 top
NOREF#610  -  []  42.06 185.73 90 top
NOREF#611  -  []  57.82 105.89 0 top
NOREF#612  -  []  35.02 300.88 0 top
NOREF#613  -  []  31.01 266.69 90 top
NOREF#614  -  []  82.73 114.89 90 top
NOREF#615  -  []  44.99 250.99 90 top
NOREF#616  -  []  68.39 193.49 45 top
NOREF#617  -  []  135.06 269.26 90 top
NOREF#618  -  []  92.17 396.29 0 top
NOREF#619  -  []  71.82 117.35 0 top
NOREF#620  -  []  161.02 336.66 0 top
NOREF#621  -  []  224.51 203.06 90 top
NOREF#622  -  []  121.39 301.68 90 top
NOREF#623  -  []  192.06 170.1 90 top
NOREF#624  -  []  194.98 281.49 90 top
NOREF#625  -  []  196.47 335.86 0 top
NOREF#626  -  []  127.54 18.69 90 top
NOREF#627  -  []  63.43 164.05 90 top
NOREF#628  -  []  160.89 240.62 90 top
NOREF#629  -  []  38.86 142.32 90 top
NOREF#630  -  []  23.93 173.3 0 top
NOREF#631  -  []  124.59 181.33 90 top
NOREF#632  -  []  102.06 183.53 90 top
NOREF#633  -  []  79.67 165.7 90 top
NOREF#634  -  []  31.4 168.9 90 top
NOREF#635  -  []  83.93 290.34 90 top
NOREF#636  -  []  247.23 199.24 90 top
NOREF#637  -  []  166.47 307.08 90 top
NOREF#638  -  []  214.59 185.73 90 top
NOREF#639  -  []  167.98 256.49 90 top
NOREF#640  -  []  25.7 198.99 90 top
NOREF#641  -  []  93.43 179.68 90 top
NOREF#642  -  []  202.98 188.49 0 top
NOREF#643  -  []  166.47 290.34 90 top
NOREF#644  -  []  60.67 176.51 90 top
NOREF#645  -  []  58.1 14.59 90 top
NOREF#646  -  []  155.02 284.14 0 top
NOREF#647  -  []  77.21 143.34 90 top
NOREF#648  -  []  50.74 275.74 0 top
NOREF#649  -  []  28.65 206.87 45 top
NOREF#650  -  []  188.86 301.68 90 top
NOREF#651  -  []  258.36 224.33 90 top
NOREF#652  -  []  188.86 188.93 0 top
NOREF#653  -  []  80.48 270.77 0 top
NOREF#654  -  []  34.6 244.47 90 top
NOREF#655  -  []  212.82 396.29 0 top
NOREF#656  -  []  225.06 269.26 90 top
NOREF#657  -  []  140.43 396.29 0 top
NOREF#658  -  []  229.67 246.67 90 top
NOREF#659  -  []  68.86 249.87 0 top
NOREF#660  -  []  19.67 246.67 90 top
NOREF#661  -  []  29.39 209.51 0 top
NOREF#662  -  []  72.06 183.53 90 top
NOREF#663  -  []  248.86 292.54 0 top
NOREF#664  -  []  28.35 207.84 315 top
NOREF#665  -  []  228.48 174.1 0 top
NOREF#666  -  []  154.59 244.47 90 top
NOREF#667  -  []  45.06 203.86 90 top
NOREF#668  -  []  94.59 246.67 90 top
NOREF#669  -  []  180.18 205.86 90 top
NOREF#670  -  []  158.86 307.08 90 top
NOREF#671  -  []  137.98 218.49 0 top
NOREF#672  -  []  58.37 267.15 315 top
NOREF#673  -  []  239.38 209.51 0 top
NOREF#674  -  []  56.96 208.69 0 top
NOREF#675  -  []  252.06 167.9 90 top
NOREF#676  -  []  121.39 171.1 90 top
NOREF#677  -  []  195.3 82.65 0 top
NOREF#678  -  []  111.43 16.49 0 top
NOREF#679  -  []  196.47 249.87 0 top
NOREF#680  -  []  45.06 209.26 90 top
NOREF#681  -  []  94.59 181.33 90 top
NOREF#682  -  []  52.99 248.49 90 top
NOREF#683  -  []  104.84 106.81 0 top
NOREF#684  -  []  181.39 249.87 0 top
NOREF#685  -  []  105.36 110.11 0 top
NOREF#686  -  []  154.59 225.98 90 top
NOREF#687  -  []  150.18 205.86 90 top
NOREF#688  -  []  240.67 176.51 90 top
NOREF#689  -  []  188.86 142.32 90 top
NOREF#690  -  []  117.64 268.84 0 top
NOREF#691  -  []  134.98 253.49 90 top
NOREF#692  -  []  225.06 207.06 90 top
NOREF#693  -  []  14.99 223.99 0 top
NOREF#694  -  []  194.3 17.15 0 top
NOREF#695  -  []  195.06 207.06 90 top
NOREF#696  -  []  76.47 173.3 0 top
NOREF#697  -  []  192.06 244.47 90 top
NOREF#698  -  []  188.69 456.29 0 top
NOREF#699  -  []  43.88 106.81 90 top
NOREF#700  -  []  147.41 138.32 0 top
NOREF#701  -  []  30.19 205.86 90 top
NOREF#702  -  []  222.06 181.33 90 top
NOREF#703  -  []  132.06 242.27 90 top
NOREF#704  -  []  63.41 234.38 0 top
NOREF#705  -  []  72.06 167.9 90 top
NOREF#706  -  []  166.47 304.88 90 top
NOREF#707  -  []  178.35 267.84 315 top
NOREF#708  -  []  87.36 268.69 0 top
NOREF#709  -  []  46.47 249.87 0 top
NOREF#710  -  []  43.91 456.29 0 top
NOREF#711  -  []  247.55 203.78 0 top
NOREF#712  -  []  165.92 284.14 90 top
NOREF#713  -  []  199.67 170.1 90 top
NOREF#714  -  []  157.23 199.24 90 top
NOREF#715  -  []  161.02 250.67 0 top
NOREF#716  -  []  218.86 144.52 90 top
NOREF#717  -  []  247.23 259.24 90 top
NOREF#718  -  []  184.59 244.47 90 top
NOREF#719  -  []  200.48 210.77 0 top
NOREF#720  -  []  226.47 335.86 0 top
NOREF#721  -  []  21.68 225.18 0 top
NOREF#722  -  []  211.01 266.69 90 top
NOREF#723  -  []  41.02 336.66 0 top
NOREF#724  -  []  102.06 289.34 90 top
NOREF#725  -  []  238.35 267.84 45 top
NOREF#726  -  []  183.41 189.73 0 top
NOREF#727  -  []  15.06 207.06 90 top
NOREF#728  -  []  224.98 223.99 0 top
NOREF#729  -  []  44.51 263.06 90 top
NOREF#730  -  []  250.89 239.1 90 top
NOREF#731  -  []  68.31 138.32 90 top
NOREF#732  -  []  203.93 225.98 90 top
NOREF#733  -  []  88.37 267.15 315 top
NOREF#734  -  []  47.99 278.49 0 top
NOREF#735  -  []  151.16 295.41 90 top
NOREF#736  -  []  248.39 253.49 45 top
NOREF#737  -  []  34.6 183.53 90 top
NOREF#738  -  []  202.98 226.49 0 top
NOREF#739  -  []  175.97 164.05 90 top
NOREF#740  -  []  167.98 278.49 0 top
NOREF#741  -  []  30.34 266.14 90 top
NOREF#742  -  []  85.94 250.67 0 top
NOREF#743  -  []  183.43 179.68 90 top
NOREF#744  -  []  118.65 206.87 45 top
NOREF#745  -  []  100.9 239.1 90 top
NOREF#746  -  []  82.99 188.49 0 top
NOREF#747  -  []  190.89 224.33 90 top
NOREF#748  -  []  34.6 287.14 90 top
NOREF#749  -  []  183.82 83.81 0 top
NOREF#750  -  []  242.56 17.15 0 top
NOREF#751  -  []  181.39 301.68 90 top
NOREF#752  -  []  151.01 206.69 90 top
NOREF#753  -  []  224.98 250.99 90 top
NOREF#754  -  []  154.64 389.27 90 top
NOREF#755  -  []  220.89 224.33 90 top
NOREF#756  -  []  76.47 225.98 90 top
NOREF#757  -  []  27.64 208.84 0 top
NOREF#758  -  []  218.31 138.32 90 top
NOREF#759  -  []  17.99 218.49 0 top
NOREF#760  -  []  222.06 246.67 90 top
NOREF#761  -  []  202.98 286.49 0 top
NOREF#762  -  []  43.46 283.29 90 top
NOREF#763  -  []  139.67 246.67 90 top
NOREF#764  -  []  148.35 267.84 45 top
NOREF#765  -  []  115.94 250.67 0 top
NOREF#766  -  []  97.55 203.78 0 top
NOREF#767  -  []  168.36 179.68 90 top
NOREF#768  -  []  175.64 106.94 0 top
NOREF#769  -  []  238.37 207.15 315 top
NOREF#770  -  []  79.67 246.67 90 top
NOREF#771  -  []  43.46 240.62 90 top
NOREF#772  -  []  127.55 203.78 0 top
NOREF#773  -  []  15.07 337.51 0 top
NOREF#774  -  []  222.06 228.18 90 top
NOREF#775  -  []  187.55 203.78 0 top
NOREF#776  -  []  211.39 171.1 90 top
NOREF#777  -  []  92.16 20.69 90 top
NOREF#778  -  []  109.67 330.46 90 top
NOREF#779  -  []  112.99 286.49 0 top
NOREF#780  -  []  109.67 165.7 90 top
NOREF#781  -  []  58.35 207.84 45 top
NOREF#782  -  []  196.47 284.94 90 top
NOREF#783  -  []  252.06 242.27 90 top
NOREF#784  -  []  68.86 301.68 0 top
NOREF#785  -  []  14.93 458.49 0 top
NOREF#786  -  []  169.67 246.67 90 top
NOREF#787  -  []  72.06 181.33 90 top
NOREF#788  -  []  158.86 301.68 90 top
NOREF#789  -  []  159.69 83.81 0 top
NOREF#790  -  []  82.99 226.49 0 top
NOREF#791  -  []  26.31 127.85 0 top
NOREF#792  -  []  205.88 237.76 90 top
NOREF#793  -  []  33.61 263.06 0 top
NOREF#794  -  []  177.36 268.69 0 top
NOREF#795  -  []  145.94 189.73 0 top
NOREF#796  -  []  106.47 290.34 90 top
NOREF#797  -  []  252.06 165.7 90 top
NOREF#798  -  []  239.29 267.51 45 top
NOREF#799  -  []  209.38 269.51 0 top
NOREF#800  -  []  154.59 242.27 90 top
NOREF#801  -  []  109.67 244.47 90 top
NOREF#802  -  []  218.86 301.68 0 top
NOREF#803  -  []  128.86 304.88 90 top
NOREF#804  -  []  252.06 244.47 90 top
NOREF#805  -  []  76.47 290.34 90 top
NOREF#806  -  []  248.31 138.32 90 top
NOREF#807  -  []  142.98 286.49 0 top
NOREF#808  -  []  49.67 242.27 90 top
NOREF#809  -  []  117.36 208.69 0 top
NOREF#810  -  []  171.17 82.65 0 top
NOREF#811  -  []  228.36 164.05 90 top
NOREF#812  -  []  87.3 16.49 0 top
NOREF#813  -  []  173.93 188.93 0 top
NOREF#814  -  []  87.13 183.53 90 top
NOREF#815  -  []  97.24 259.24 90 top
NOREF#816  -  []  67.24 259.24 90 top
NOREF#817  -  []  177.13 244.47 90 top
NOREF#818  -  []  199.94 300.88 0 top
NOREF#819  -  []  31.96 297.11 0 top
NOREF#820  -  []  178.44 14.59 90 top
NOREF#821  -  []  241.39 304.88 90 top
NOREF#822  -  []  155.02 225.18 0 top
NOREF#823  -  []  241.39 249.87 0 top
NOREF#824  -  []  26.39 82.65 0 top
NOREF#825  -  []  192.06 181.33 90 top
NOREF#826  -  []  199.94 454.29 90 top
NOREF#827  -  []  212.81 18.69 0 top
NOREF#828  -  []  154.59 284.94 90 top
NOREF#829  -  []  241.39 233.58 0 top
NOREF#830  -  []  108.36 224.33 90 top
NOREF#831  -  []  119.29 207.51 45 top
NOREF#832  -  []  218.86 188.93 0 top
NOREF#833  -  []  241.39 171.1 90 top
NOREF#834  -  []  46.47 290.34 90 top
NOREF#835  -  []  238.37 267.15 315 top
NOREF#836  -  []  169.19 392.33 90 top
NOREF#837  -  []  244.59 228.18 90 top
NOREF#838  -  []  58.65 206.87 45 top
NOREF#839  -  []  15.06 269.26 90 top
NOREF#840  -  []  241.16 295.41 90 top
NOREF#841  -  []  153.41 293.34 0 top
NOREF#842  -  []  91.01 206.29 90 top
NOREF#843  -  []  145.97 326.61 90 top
NOREF#844  -  []  172.76 106.73 0 top
NOREF#845  -  []  229.67 332.66 90 top
NOREF#846  -  []  211.16 295.41 90 top
NOREF#847  -  []  162.06 289.34 90 top
NOREF#848  -  []  183.41 250.67 0 top
NOREF#849  -  []  243.41 174.1 0 top
NOREF#850  -  []  236.95 456.29 90 top
NOREF#851  -  []  78.36 283.29 90 top
NOREF#852  -  []  145.97 240.62 90 top
NOREF#853  -  []  75.06 267.06 90 top
NOREF#854  -  []  74.65 82.65 0 top
NOREF#855  -  []  162.06 185.73 90 top
NOREF#856  -  []  109.67 332.66 90 top
NOREF#857  -  []  207.78 269.51 0 top
NOREF#858  -  []  20.74 215.74 0 top
NOREF#859  -  []  180.65 236.45 90 top
NOREF#860  -  []  105.06 209.26 90 top
NOREF#861  -  []  168.48 189.73 0 top
NOREF#862  -  []  164.51 203.06 90 top
NOREF#863  -  []  175.94 250.67 0 top
NOREF#864  -  []  109.67 328.26 90 top
NOREF#865  -  []  158.86 249.87 0 top
NOREF#866  -  []  26.31 123.41 90 top
NOREF#867  -  []  115.94 293.34 0 top
NOREF#868  -  []  248.31 300.88 90 top
NOREF#869  -  []  147.13 303.88 90 top
NOREF#870  -  []  29.39 269.51 0 top
NOREF#871  -  []  42.06 183.53 90 top
NOREF#872  -  []  123.41 189.73 0 top
NOREF#873  -  []  30.51 105.11 90 top
NOREF#874  -  []  42.06 287.14 90 top
NOREF#875  -  []  107.99 196.49 90 top
NOREF#876  -  []  243.43 164.05 90 top
NOREF#877  -  []  198.36 240.62 90 top
NOREF#878  -  []  19.67 330.46 90 top
NOREF#879  -  []  43.88 117.35 0 top
NOREF#880  -  []  58.35 267.84 315 top
NOREF#881  -  []  184.59 284.94 90 top
NOREF#882  -  []  153.41 250.67 0 top
NOREF#883  -  []  79.67 185.73 90 top
NOREF#884  -  []  120.84 300.88 90 top
NOREF#885  -  []  23.93 225.98 0 top
NOREF#886  -  []  26.58 124.95 90 top
NOREF#887  -  []  147.13 167.9 90 top
NOREF#888  -  []  46.47 307.08 90 top
NOREF#889  -  []  132.06 170.1 90 top
NOREF#890  -  []  46.47 188.93 0 top
NOREF#891  -  []  19.67 183.53 90 top
NOREF#892  -  []  120.84 164.9 90 top
NOREF#893  -  []  207.13 183.53 90 top
NOREF#894  -  []  158.86 188.93 0 top
NOREF#895  -  []  40.9 179.68 90 top
NOREF#896  -  []  226.47 188.93 0 top
NOREF#897  -  []  75.92 225.18 90 top
NOREF#898  -  []  16.15 127.85 0 top
NOREF#899  -  []  55.95 250.67 0 top
NOREF#900  -  []  164.98 253.49 90 top
NOREF#901  -  []  214.59 289.34 90 top
NOREF#902  -  []  138.48 310.08 0 top
NOREF#903  -  []  226.47 301.68 90 top
NOREF#904  -  []  85.97 240.62 90 top
NOREF#905  -  []  222.06 289.34 90 top
NOREF#906  -  []  163.73 107.06 0 top
NOREF#907  -  []  237.13 170.1 90 top
NOREF#908  -  []  241.39 292.54 0 top
NOREF#909  -  []  196.47 290.34 90 top
NOREF#910  -  []  164.98 250.99 90 top
NOREF#911  -  []  180.67 176.51 90 top
NOREF#912  -  []  72.34 120.65 0 top
NOREF#913  -  []  138.18 452.29 90 top
NOREF#914  -  []  42.06 165.7 90 top
NOREF#915  -  []  173.93 225.98 90 top
NOREF#916  -  []  58.12 389.27 90 top
NOREF#917  -  []  165.06 267.06 90 top
NOREF#918  -  []  198.36 283.29 90 top
NOREF#919  -  []  143.93 188.93 0 top
NOREF#920  -  []  139.67 170.1 90 top
NOREF#921  -  []  184.59 289.34 90 top
NOREF#922  -  []  175.97 326.61 90 top
NOREF#923  -  []  178.35 207.84 45 top
NOREF#924  -  []  109.67 246.67 90 top
NOREF#925  -  []  45.06 263.86 0 top
NOREF#926  -  []  175.88 237.76 90 top
NOREF#927  -  []  207.13 165.7 90 top
NOREF#928  -  []  72.48 225.18 0 top
NOREF#929  -  []  233.93 231.38 90 top
NOREF#930  -  []  49.67 328.26 90 top
NOREF#931  -  []  15.06 203.86 0 top
NOREF#932  -  []  181.39 188.93 0 top
NOREF#933  -  []  211.39 292.54 0 top
NOREF#934  -  []  203.93 229.18 90 top
NOREF#935  -  []  154.59 181.33 90 top
NOREF#936  -  []  145.06 392.33 90 top
NOREF#937  -  []  127.23 199.24 90 top
NOREF#938  -  []  87.13 170.1 90 top
NOREF#939  -  []  251.4 298.06 90 top
NOREF#940  -  []  214.59 242.27 90 top
NOREF#941  -  []  68.86 142.32 90 top
NOREF#942  -  []  30.65 236.45 90 top
NOREF#943  -  []  145.97 164.05 90 top
NOREF#944  -  []  72.06 225.98 90 top
NOREF#945  -  []  178.37 207.15 315 top
NOREF#946  -  []  98.86 249.87 0 top
NOREF#947  -  []  73.65 17.15 90 top
NOREF#948  -  []  128.86 139.12 0 top
NOREF#949  -  []  244.59 244.47 90 top
NOREF#950  -  []  13.66 262.21 0 top
NOREF#951  -  []  53.93 188.93 0 top
NOREF#952  -  []  233.93 249.87 0 top
NOREF#953  -  []  77.46 112.09 90 top
NOREF#954  -  []  63.43 179.68 90 top
NOREF#955  -  []  117.13 167.9 90 top
NOREF#956  -  []  136.47 304.88 90 top
NOREF#957  -  []  31.4 301.68 90 top
NOREF#958  -  []  30.19 265.47 90 top
NOREF#959  -  []  218.86 142.32 90 top
NOREF#960  -  []  68.39 253.49 45 top
NOREF#961  -  []  119.41 115.65 90 top
NOREF#962  -  []  55.15 18.69 90 top
NOREF#963  -  []  166.47 284.94 0 top
NOREF#964  -  []  143.93 288.14 90 top
NOREF#965  -  []  139.94 164.9 0 top
NOREF#966  -  []  120.65 236.45 90 top
NOREF#967  -  []  125.02 284.14 0 top
NOREF#968  -  []  108.48 310.08 0 top
NOREF#969  -  []  188.69 456.29 90 top
NOREF#970  -  []  117.41 138.32 0 top
NOREF#971  -  []  102.06 170.1 90 top
NOREF#972  -  []  128.66 177.76 90 top
NOREF#973  -  []  215.02 225.18 0 top
NOREF#974  -  []  63.61 263.06 0 top
NOREF#975  -  []  229.67 185.73 90 top
NOREF#976  -  []  68.04 456.29 90 top
NOREF#977  -  []  102.06 165.7 90 top
NOREF#978  -  []  23.93 284.94 90 top
NOREF#979  -  []  235.7 258.99 90 top
NOREF#980  -  []  72.06 228.18 90 top
NOREF#981  -  []  143.93 309.28 0 top
NOREF#982  -  []  68.86 233.58 0 top
NOREF#983  -  []  213.43 240.62 90 top
NOREF#984  -  []  104.99 250.99 90 top
NOREF#985  -  []  173.38 284.14 90 top
NOREF#986  -  []  85.94 189.73 0 top
NOREF#987  -  []  61.4 171.1 90 top
NOREF#988  -  []  49.67 183.53 90 top
NOREF#989  -  []  222.06 165.7 90 top
NOREF#990  -  []  77.99 278.49 0 top
NOREF#991  -  []  103.41 18.69 90 top
NOREF#992  -  []  222.06 183.53 90 top
NOREF#993  -  []  106.47 229.18 90 top
NOREF#994  -  []  132.06 183.53 90 top
NOREF#995  -  []  26.68 239.46 0 top
NOREF#996  -  []  106.47 173.3 0 top
NOREF#997  -  []  128.73 110.11 90 top
NOREF#998  -  []  104.99 253.49 90 top
NOREF#999  -  []  104.51 203.06 90 top
NOREF#1000  -  []  49.95 164.9 0 top
NOREF#1001  -  []  202.56 389.27 90 top
NOREF#1002  -  []  29.29 267.51 45 top
NOREF#1003  -  []  123.41 174.1 0 top
NOREF#1004  -  []  61.4 233.58 0 top
NOREF#1005  -  []  153.43 164.05 90 top
NOREF#1006  -  []  64.59 181.33 90 top
NOREF#1007  -  []  76.47 249.87 0 top
NOREF#1008  -  []  47.99 218.49 0 top
NOREF#1009  -  []  104.99 281.49 90 top
NOREF#1010  -  []  240.84 164.9 90 top
NOREF#1011  -  []  36.61 138.32 0 top
NOREF#1012  -  []  166.47 335.86 0 top
NOREF#1013  -  []  29.29 207.51 45 top
NOREF#1014  -  []  194.98 193.49 90 top
NOREF#1015  -  []  167.21 143.34 90 top
NOREF#1016  -  []  90.18 265.47 90 top
NOREF#1017  -  []  109.67 170.1 90 top
NOREF#1018  -  []  248.86 139.12 0 top
NOREF#1019  -  []  19.67 170.1 90 top
NOREF#1020  -  []  229.67 330.46 90 top
NOREF#1021  -  []  117.41 300.88 0 top
NOREF#1022  -  []  168.36 283.29 90 top
NOREF#1023  -  []  172.98 226.49 0 top
NOREF#1024  -  []  72.06 170.1 90 top
NOREF#1025  -  []  214.59 181.33 90 top
NOREF#1026  -  []  229.67 244.47 90 top
NOREF#1027  -  []  46.47 288.14 90 top
NOREF#1028  -  []  63.18 16.49 0 top
NOREF#1029  -  []  184.59 230.38 90 top
NOREF#1030  -  []  211.39 249.87 0 top
NOREF#1031  -  []  228.36 179.68 90 top
NOREF#1032  -  []  49.67 330.46 90 top
NOREF#1033  -  []  91.4 301.68 0 top
NOREF#1034  -  []  172.98 188.49 0 top
NOREF#1035  -  []  31.4 304.88 90 top
NOREF#1036  -  []  258.36 164.05 90 top
NOREF#1037  -  []  27.36 208.69 0 top
NOREF#1038  -  []  37.24 199.24 90 top
NOREF#1039  -  []  198.36 224.33 90 top
NOREF#1040  -  []  122.16 115.65 0 top
NOREF#1041  -  []  181.39 165.7 90 top
NOREF#1042  -  []  96.8 392.33 90 top
NOREF#1043  -  []  149.32 268.11 315 top
NOREF#1044  -  []  164.51 263.06 90 top
NOREF#1045  -  []  59.39 269.51 0 top
NOREF#1046  -  []  132.06 287.14 90 top
NOREF#1047  -  []  42.06 230.38 90 top
NOREF#1048  -  []  57.79 269.51 0 top
NOREF#1049  -  []  29.15 164.9 0 top
NOREF#1050  -  []  19.67 242.27 90 top
NOREF#1051  -  []  150.84 164.9 90 top
NOREF#1052  -  []  30.67 176.51 90 top
NOREF#1053  -  []  60.19 205.47 90 top
NOREF#1054  -  []  47.99 196.49 90 top
NOREF#1055  -  []  205.97 179.68 90 top
NOREF#1056  -  []  258.36 240.62 90 top
NOREF#1057  -  []  16.47 284.94 0 top
NOREF#1058  -  []  160.9 237.58 90 top
NOREF#1059  -  []  65.02 284.14 0 top
NOREF#1060  -  []  124.59 289.34 90 top
NOREF#1061  -  []  192.06 228.18 90 top
NOREF#1062  -  []  208.35 207.84 45 top
NOREF#1063  -  []  49.67 332.66 90 top
NOREF#1064  -  []  226.47 307.08 90 top
NOREF#1065  -  []  183.43 164.05 90 top
NOREF#1066  -  []  248.19 18.69 90 top
NOREF#1067  -  []  180.18 205.47 90 top
NOREF#1068  -  []  14.51 203.06 90 top
NOREF#1069  -  []  72.06 289.34 90 top
NOREF#1070  -  []  57.13 242.27 90 top
NOREF#1071  -  []  132.06 181.33 90 top
NOREF#1072  -  []  183.41 174.1 0 top
NOREF#1073  -  []  169.67 244.47 90 top
NOREF#1074  -  []  226.47 301.68 0 top
NOREF#1075  -  []  79.67 328.26 90 top
NOREF#1076  -  []  166.47 173.3 0 top
NOREF#1077  -  []  20.49 270.77 0 top
NOREF#1078  -  []  226.47 225.98 90 top
NOREF#1079  -  []  148.37 207.15 315 top
NOREF#1080  -  []  115.94 234.38 0 top
NOREF#1081  -  []  132.48 284.14 0 top
NOREF#1082  -  []  151.01 266.29 90 top
NOREF#1083  -  []  42.06 246.67 90 top
NOREF#1084  -  []  142.98 188.49 0 top
NOREF#1085  -  []  224.51 263.06 90 top
NOREF#1086  -  []  108.36 179.68 90 top
NOREF#1087  -  []  61.4 165.7 90 top
NOREF#1088  -  []  100.89 179.68 90 top
NOREF#1089  -  []  226.47 231.38 90 top
NOREF#1090  -  []  91.4 233.58 0 top
NOREF#1091  -  []  91.4 249.87 0 top
NOREF#1092  -  []  63.43 300.03 90 top
NOREF#1093  -  []  64.59 183.53 90 top
NOREF#1094  -  []  29.15 164.9 90 top
NOREF#1095  -  []  127.23 259.24 90 top
NOREF#1096  -  []  74.51 263.06 90 top
NOREF#1097  -  []  237.36 208.69 0 top
NOREF#1098  -  []  79.67 330.46 90 top
NOREF#1099  -  []  194.51 263.06 90 top
NOREF#1100  -  []  181.39 292.54 0 top
NOREF#1101  -  []  194.98 250.99 90 top
NOREF#1102  -  []  133.01 240.57 90 top
NOREF#1103  -  []  236.96 208.69 0 top
NOREF#1104  -  []  175.97 240.62 90 top
NOREF#1105  -  []  80.48 210.77 0 top
NOREF#1106  -  []  134.98 221.49 90 top
NOREF#1107  -  []  25.95 234.38 0 top
NOREF#1108  -  []  149.39 209.51 0 top
NOREF#1109  -  []  162.06 287.14 90 top
NOREF#1110  -  []  121.39 165.7 90 top
NOREF#1111  -  []  203.93 225.98 0 top
NOREF#1112  -  []  87.64 208.84 0 top
NOREF#1113  -  []  85.88 237.76 90 top
NOREF#1114  -  []  85.7 258.99 90 top
NOREF#1115  -  []  14.99 281.49 90 top
NOREF#1116  -  []  136.47 188.93 0 top
NOREF#1117  -  []  107.99 218.49 0 top
NOREF#1118  -  []  94.59 183.53 90 top
NOREF#1119  -  []  218.86 139.12 90 top
NOREF#1120  -  []  61.16 295.41 90 top
NOREF#1121  -  []  244.59 246.67 90 top
NOREF#1122  -  []  67.55 263.78 0 top
NOREF#1123  -  []  116.29 18.69 0 top
NOREF#1124  -  []  91.16 295.41 90 top
NOREF#1125  -  []  82.99 188.49 90 top
NOREF#1126  -  []  199.67 244.47 90 top
NOREF#1127  -  []  102.06 230.38 90 top
NOREF#1128  -  []  95.02 300.88 0 top
NOREF#1129  -  []  132.78 117.35 90 top
NOREF#1130  -  []  166.47 288.14 90 top
NOREF#1131  -  []  188.39 253.49 45 top
NOREF#1132  -  []  226.69 14.59 90 top
NOREF#1133  -  []  173.93 284.94 90 top
NOREF#1134  -  []  33.26 105.11 0 top
NOREF#1135  -  []  185.02 300.88 0 top
NOREF#1136  -  []  193.32 392.33 90 top
NOREF#1137  -  []  42.06 289.34 90 top
NOREF#1138  -  []  76.47 188.93 0 top
NOREF#1139  -  []  190.89 179.68 90 top
NOREF#1140  -  []  57.13 301.68 90 top
NOREF#1141  -  []  180.33 266.14 90 top
NOREF#1142  -  []  87.13 246.67 90 top
NOREF#1143  -  []  175.64 103.13 90 top
NOREF#1144  -  []  203.93 249.87 0 top
NOREF#1145  -  []  83.93 309.28 0 top
NOREF#1146  -  []  68.66 177.76 90 top
NOREF#1147  -  []  239.29 207.51 45 top
NOREF#1148  -  []  79.67 181.33 90 top
NOREF#1149  -  []  139.67 165.7 90 top
NOREF#1150  -  []  27.13 183.53 90 top
NOREF#1151  -  []  181.01 266.69 90 top
NOREF#1152  -  []  82.99 286.49 0 top
NOREF#1153  -  []  55.95 234.38 0 top
NOREF#1154  -  []  116.96 268.69 0 top
NOREF#1155  -  []  207.13 242.27 90 top
NOREF#1156  -  []  93.61 203.06 0 top
NOREF#1157  -  []  53.38 225.18 90 top
NOREF#1158  -  []  44.51 203.06 90 top
NOREF#1159  -  []  102.06 167.9 90 top
NOREF#1160  -  []  241.58 392.33 90 top
NOREF#1161  -  []  153.61 203.06 0 top
NOREF#1162  -  []  211.39 307.08 90 top
NOREF#1163  -  []  173.38 225.18 90 top
NOREF#1164  -  []  98.39 193.49 45 top
NOREF#1165  -  []  214.59 284.94 90 top
NOREF#1166  -  []  111.45 458.49 0 top
NOREF#1167  -  []  218.39 253.49 45 top
NOREF#1168  -  []  109.67 183.53 90 top
NOREF#1169  -  []  222.06 244.47 90 top
NOREF#1170  -  []  47.21 143.34 90 top
NOREF#1171  -  []  16.47 188.93 0 top
NOREF#1172  -  []  226.47 284.94 0 top
NOREF#1173  -  []  192.06 284.94 90 top
NOREF#1174  -  []  237.13 303.88 90 top
NOREF#1175  -  []  165.06 209.26 90 top
NOREF#1176  -  []  30.51 115.65 90 top
NOREF#1177  -  []  98.66 177.76 90 top
NOREF#1178  -  []  164.56 456.29 0 top
NOREF#1179  -  []  161.4 296.54 90 top
NOREF#1180  -  []  165.06 263.86 0 top
NOREF#1181  -  []  38.51 105.11 0 top
NOREF#1182  -  []  121.01 206.69 90 top
NOREF#1183  -  []  194.98 253.49 90 top
NOREF#1184  -  []  48.48 189.73 0 top
NOREF#1185  -  []  181.16 295.41 90 top
NOREF#1186  -  []  70.89 240.62 90 top
NOREF#1187  -  []  138.48 189.73 0 top
NOREF#1188  -  []  168.36 224.33 90 top
NOREF#1189  -  []  76.47 301.68 0 top
NOREF#1190  -  []  50.74 215.74 0 top
NOREF#1191  -  []  99.47 105.11 0 top
NOREF#1192  -  []  70.89 179.68 90 top
NOREF#1193  -  []  233.93 284.94 90 top
NOREF#1194  -  []  98.39 253.49 45 top
NOREF#1195  -  []  121.01 266.29 90 top
NOREF#1196  -  []  162.66 107.36 0 top
NOREF#1197  -  []  195.06 209.26 90 top
NOREF#1198  -  []  218.43 17.15 0 top
NOREF#1199  -  []  106.47 301.68 0 top
NOREF#1200  -  []  194.98 281.49 90 top
NOREF#1201  -  []  143.93 284.94 0 top
NOREF#1202  -  []  64.59 225.98 90 top
NOREF#1203  -  []  105.92 300.88 90 top
NOREF#1204  -  []  112.99 188.49 90 top
NOREF#1205  -  []  42.06 284.94 90 top
NOREF#1206  -  []  23.93 284.94 0 top
NOREF#1207  -  []  113.93 231.38 90 top
NOREF#1208  -  []  104.84 106.81 90 top
NOREF#1209  -  []  34.6 242.27 90 top
NOREF#1210  -  []  118.35 207.84 315 top
NOREF#1211  -  []  192.48 284.14 0 top
